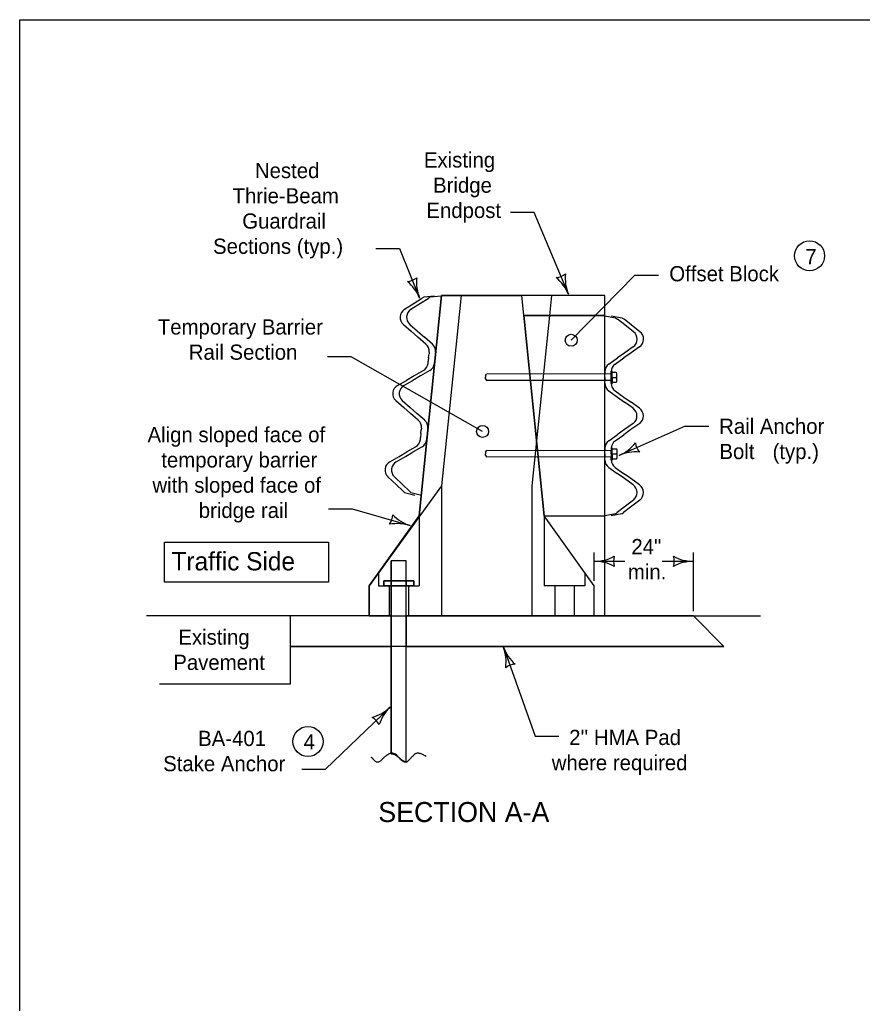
# Model space of a CAD drawing. Extents: x 10028 to 81668, y 3581 to 11018.
# Drawn here: x 17333 to 18174, y 8962 to 9944 of the extents above; entities that cross this region are included whole.
import ezdxf

# ---------------------------------------------------------------- set-up
doc = ezdxf.new("R2010")
doc.units = 0
for name, color, linetype in [('conPaving', 7, 'Continuous'), ('dsnCellsNorthArrow', 7, 'Continuous'), ('dsnTextTabulation', 7, 'Continuous'), ('Level 41', 7, 'Continuous'), ('Level 9', 7, 'Continuous'), ('SheetBorder', 7, 'Continuous')]:
    doc.layers.add(name, color=color, linetype=linetype)

msp = doc.modelspace()

# ---------------------------------------------------------------- linework, layer by layer
at = {"layer": 'conPaving'}
for p, q in [((17753.7, 9478.52), (17753.7, 9348.52)), ((17844.13, 9478.52), (17844.13, 9348.52))]:
    msp.add_line(p, q, dxfattribs=at)
at = {"layer": 'dsnCellsNorthArrow'}
for p, q in [((17773.43, 9668.41), (17753.7, 9478.52)), ((17916.97, 9668.41), (17773.43, 9668.41)), ((17863.86, 9668.41), (17861.79, 9648.52)), ((17916.97, 9348.63), (17916.97, 9668.41)), ((17861.79, 9648.52), (17844.13, 9478.52)), ((17753.7, 9478.52), (17681.45, 9378.52)), ((17681.45, 9348.52), (17681.45, 9378.52))]:
    msp.add_line(p, q, dxfattribs=at)
at = {"layer": 'dsnTextTabulation'}
for p, q in [((17846.24, 9751.44), (17822.63, 9751.44)), ((17880.56, 9669.84), (17846.24, 9751.44)), ((17688.2, 9715.55), (17711.8, 9715.55)), ((17711.8, 9715.55), (17732.03, 9665.97)), ((17883.39, 9623.84), (17946.85, 9688.92)), ((17946.85, 9688.92), (17970.49, 9688.92)), ((17731.45, 9448.52), (17753.95, 9668.52)), ((17736.25, 9666.95), (17734.02, 9665.54)), ((17746.96, 9667.77), (17736.25, 9666.95)), ((17742.65, 9666.95), (17740.42, 9665.54)), ((17753.36, 9667.77), (17742.65, 9666.95)), ((17753.95, 9668.52), (17833.95, 9668.52)), ((17856.45, 9448.52), (17833.95, 9668.52)), ((17716.98, 9654.79), (17726.48, 9660.78)), ((17723.38, 9654.79), (17732.88, 9660.78)), ((17726.48, 9660.78), (17734.02, 9665.54)), ((17732.88, 9660.78), (17740.42, 9665.54)), ((17917.13, 9648.3), (17927.71, 9646.42)), ((17923.53, 9648.3), (17934.1, 9646.42)), ((17927.71, 9646.42), (17929.79, 9644.8)), ((17934.1, 9646.42), (17936.18, 9644.8)), ((17715.82, 9639.74), (17723.62, 9632.93)), ((17722.22, 9639.74), (17730.02, 9632.93)), ((17936.82, 9639.31), (17929.79, 9644.8)), ((17943.21, 9639.31), (17936.18, 9644.8)), ((17945.67, 9632.4), (17936.82, 9639.31)), ((17952.07, 9632.4), (17943.21, 9639.31)), ((17723.62, 9632.93), (17730.33, 9627.08)), ((17730.02, 9632.93), (17736.73, 9627.08)), ((17738.34, 9620.09), (17730.33, 9627.08)), ((17744.74, 9620.09), (17736.73, 9627.08)), ((17945.33, 9617.31), (17936.89, 9611.32)), ((17951.72, 9617.31), (17943.29, 9611.32)), ((17663.62, 9607.48), (17640.02, 9607.48)), ((17794.92, 9532.77), (17663.62, 9607.48)), ((17740.98, 9606.45), (17741.36, 9610.33)), ((17741.53, 9612.08), (17741.36, 9610.33)), ((17747.38, 9606.45), (17747.76, 9610.33)), ((17747.93, 9612.08), (17747.76, 9610.33)), ((17936.89, 9611.32), (17929.62, 9606.16)), ((17943.29, 9611.32), (17936.02, 9606.16)), ((17740.44, 9600.82), (17740.63, 9602.86)), ((17741, 9606.59), (17740.63, 9602.86)), ((17746.83, 9600.82), (17747.03, 9602.86)), ((17747.39, 9606.59), (17747.03, 9602.86)), ((17920.96, 9600), (17929.62, 9606.16)), ((17927.36, 9600), (17936.02, 9606.16)), ((17726.57, 9588.28), (17718.85, 9583.83)), ((17732.97, 9588.28), (17725.25, 9583.83)), ((17735.76, 9593.58), (17726.57, 9588.28)), ((17742.16, 9593.58), (17732.97, 9588.28)), ((17916.97, 9586.69), (17916.98, 9590.59)), ((17916.99, 9592.35), (17916.98, 9590.59)), ((17923.37, 9586.69), (17923.38, 9590.59)), ((17923.39, 9592.35), (17923.38, 9590.59)), ((17709.87, 9578.65), (17718.85, 9583.83)), ((17716.26, 9578.65), (17725.25, 9583.83)), ((17916.96, 9581.03), (17916.97, 9583.08)), ((17916.97, 9586.83), (17916.97, 9583.08)), ((17923.37, 9586.83), (17923.36, 9583.08)), ((17923.36, 9581.03), (17923.36, 9583.08)), ((17920.89, 9573.36), (17929.51, 9567.18)), ((17927.29, 9573.36), (17935.9, 9567.18)), ((17708.12, 9563.63), (17716.2, 9556.59)), ((17714.52, 9563.63), (17722.6, 9556.59)), ((17929.51, 9567.18), (17936.74, 9561.98)), ((17935.9, 9567.18), (17943.14, 9561.98)), ((17945.17, 9555.93), (17936.74, 9561.98)), ((17951.57, 9555.93), (17943.14, 9561.98)), ((17716.2, 9556.59), (17722.91, 9550.73)), ((17722.6, 9556.59), (17729.31, 9550.73)), ((17730.65, 9543.98), (17722.91, 9550.73)), ((17737.04, 9543.98), (17729.31, 9550.73)), ((17945.41, 9540.82), (17936.67, 9534.61)), ((17951.81, 9540.82), (17943.07, 9534.61)), ((17733.32, 9530.66), (17732.96, 9526.93)), ((17733.32, 9530.66), (17733.68, 9534.4)), ((17733.84, 9535.98), (17733.68, 9534.4)), ((17739.72, 9530.66), (17739.35, 9526.93)), ((17739.72, 9530.66), (17740.08, 9534.4)), ((17740.23, 9535.98), (17740.08, 9534.4)), ((17921.04, 9523.51), (17929.41, 9529.45)), ((17927.44, 9523.51), (17935.8, 9529.45)), ((17936.67, 9534.61), (17929.41, 9529.45)), ((17997.16, 9537.94), (17931.26, 9508.86)), ((17943.07, 9534.61), (17935.8, 9529.45)), ((17997.16, 9537.94), (18020.77, 9537.94)), ((17732.74, 9524.71), (17732.96, 9526.93)), ((17739.14, 9524.71), (17739.35, 9526.93)), ((17711.45, 9507.9), (17719.17, 9512.35)), ((17717.85, 9507.9), (17725.57, 9512.35)), ((17728.06, 9517.47), (17719.17, 9512.35)), ((17734.46, 9517.47), (17725.57, 9512.35)), ((17917.05, 9510.52), (17917.06, 9514.27)), ((17917.05, 9510.52), (17917.05, 9506.76)), ((17917.07, 9515.86), (17917.06, 9514.27)), ((17923.45, 9510.52), (17923.44, 9506.76)), ((17923.45, 9510.52), (17923.46, 9514.27)), ((17923.47, 9515.86), (17923.46, 9514.27)), ((17702.17, 9502.55), (17711.45, 9507.9)), ((17708.57, 9502.55), (17717.85, 9507.9)), ((17917.04, 9504.54), (17917.05, 9506.76)), ((17923.44, 9504.54), (17923.44, 9506.76)), ((17920.97, 9496.87), (17929.31, 9490.88)), ((17927.37, 9496.87), (17935.71, 9490.88)), ((17936.55, 9485.69), (17929.31, 9490.88)), ((17942.95, 9485.69), (17935.71, 9490.88)), ((17700.4, 9487.55), (17708.81, 9479.61)), ((17706.8, 9487.55), (17715.2, 9479.61)), ((17708.81, 9479.61), (17715.29, 9473.48)), ((17715.2, 9479.61), (17721.69, 9473.48)), ((17945.25, 9479.44), (17936.55, 9485.69)), ((17951.65, 9479.44), (17942.95, 9485.69)), ((17716.96, 9471.9), (17715.29, 9473.48)), ((17716.96, 9471.9), (17727.31, 9469.03)), ((17723.36, 9471.9), (17721.69, 9473.48)), ((17723.36, 9471.9), (17733.71, 9469.03)), ((17945.52, 9464.34), (17936.36, 9457.28)), ((17951.91, 9464.34), (17942.76, 9457.28)), ((17640.93, 9455.58), (17664.54, 9455.58)), ((17664.54, 9455.58), (17722.64, 9438.73)), ((17927.48, 9450.42), (17916.9, 9448.59)), ((17933.88, 9450.42), (17923.29, 9448.59)), ((17927.48, 9450.42), (17929.3, 9451.82)), ((17936.36, 9457.28), (17929.3, 9451.83)), ((17933.88, 9450.42), (17935.7, 9451.82)), ((17942.76, 9457.28), (17935.7, 9451.83)), ((17681.45, 9378.52), (17731.45, 9448.52)), ((17906.45, 9378.52), (17856.45, 9448.52)), ((17906.45, 9383.51), (17906.45, 9411.87)), ((18005.49, 9353.28), (18005.49, 9411.87)), ((17906.45, 9403.11), (17936.86, 9403.11)), ((17974.18, 9403.11), (18005.49, 9403.11)), ((17681.45, 9348.52), (17681.45, 9378.52)), ((17906.45, 9348.52), (17906.45, 9378.52)), ((17681.45, 9348.52), (17906.45, 9348.52)), ((17815.75, 9317.4), (17847.38, 9228.36)), ((17638.11, 9195.72), (17702.53, 9257.52)), ((17847.38, 9228.36), (17870.98, 9228.36)), ((17614.5, 9195.72), (17638.11, 9195.72))]:
    msp.add_line(p, q, dxfattribs=at)
for centre in [(18121.45, 9708.22), (17620.5, 9223.19)]:
    msp.add_circle(centre, 15, dxfattribs=at)
for centre, radius, start, end in [((17718.57, 9698.97), 16.42, 274.46679, 309.93349), ((17771.38, 9682.03), 42.5, 174.12765, 202.20014), ((17867.11, 9702.84), 16.42, 274.42912, 309.89582), ((17841.2, 9653.8), 42.5, 22.16247, 50.23496), ((17919.92, 9685.87), 42.5, 174.08998, 202.16247), ((17692.68, 9649.92), 42.5, 22.20014, 50.27263), ((17914.25, 9547.8), 42.5, 293.59825, 321.67074), ((17963.92, 9523.12), 16.42, 185.8649, 221.3316), ((17948.28, 9469.91), 42.5, 85.52576, 113.59825), ((17688.71, 9449.63), 16.42, 324.45544, 359.92214), ((17709.64, 9398.27), 42.5, 72.18879, 100.26128), ((17735.64, 9479.19), 42.5, 224.1163, 252.18879), ((17906.45, 9445.61), 42.5, 270, 298.07249), ((17906.45, 9360.61), 42.5, 61.92751, 90), ((17942.09, 9403.11), 16.42, 162.26665, 197.73335), ((17969.85, 9403.11), 16.42, 342.26665, 17.73335), ((18005.49, 9445.61), 42.5, 241.92751, 270), ((18005.49, 9360.61), 42.5, 90, 118.07249), ((17855.63, 9332.08), 42.5, 200.20763, 228.28012), ((17775.86, 9302.72), 42.5, 352.13514, 20.20763), ((17828.05, 9283.96), 16.42, 92.47427, 127.94098), ((17673.1, 9288.19), 42.5, 285.73709, 313.80957), ((17731.95, 9226.85), 42.5, 133.80957, 161.88206), ((17676.81, 9232.85), 16.42, 26.07622, 61.54292)]:
    msp.add_arc(centre, radius, start, end, dxfattribs=at)
for centre, major_axis, start_param, end_param in [((17722.06, 9646.83), (9.43, -0.92), 2.229659, 4.096128), ((17728.46, 9646.83), (9.43, -0.92), 2.229659, 4.096128), ((17939.82, 9624.98), (-9.48, 0.02), 2.187057, 4.053527), ((17946.22, 9624.98), (-9.48, 0.02), 2.187057, 4.053527), ((17732.1, 9613), (9.43, -0.92), 0, 0.954538), ((17738.5, 9613), (9.43, -0.92), 0, 0.954538), ((17731, 9601.74), (-9.43, 0.92), 2.187055, 3.141593), ((17737.4, 9601.74), (-9.43, 0.92), 2.187055, 3.141593), ((17926.47, 9592.33), (-9.48, 0.02), 5.328647, 6.283185), ((17932.86, 9592.33), (-9.48, 0.02), 5.328647, 6.283185), ((17714.62, 9570.49), (-9.43, 0.92), 5.32865, 7.195119), ((17721.02, 9570.49), (-9.43, 0.92), 5.32865, 7.195119), ((17926.44, 9581.01), (9.48, -0.02), 3.141593, 4.096131), ((17932.83, 9581.01), (9.48, -0.02), 3.141593, 4.096131), ((17939.62, 9548.29), (9.48, -0.02), 5.371251, 7.237721), ((17946.02, 9548.29), (9.48, -0.02), 5.371251, 7.237721), ((17724.4, 9536.9), (9.43, -0.92), 0, 0.954538), ((17730.8, 9536.9), (9.43, -0.92), 0, 0.954538), ((17723.31, 9525.63), (-9.43, 0.92), 2.187055, 3.141593), ((17729.7, 9525.63), (-9.43, 0.92), 2.187055, 3.141593), ((17926.55, 9515.83), (-9.48, 0.02), 5.328647, 6.283185), ((17932.94, 9515.83), (-9.48, 0.02), 5.328647, 6.283185), ((17706.93, 9494.38), (-9.43, 0.92), 5.32865, 7.195119), ((17713.32, 9494.38), (-9.43, 0.92), 5.32865, 7.195119), ((17926.52, 9504.52), (9.48, -0.02), 3.141593, 4.096131), ((17932.92, 9504.52), (9.48, -0.02), 3.141593, 4.096131), ((17939.7, 9471.79), (9.48, -0.02), 5.371251, 7.237721), ((17946.1, 9471.79), (9.48, -0.02), 5.371251, 7.237721)]:
    msp.add_ellipse(centre, major_axis=major_axis, ratio=0.994906, start_param=start_param, end_param=end_param, dxfattribs=at)
at = {"layer": 'Level 41'}
for p, q in [((17731.45, 9448.52), (17731.45, 9378.52)), ((17856.45, 9448.52), (17856.45, 9378.52)), ((17690.98, 9391.86), (17690.98, 9378.52)), ((17896.92, 9391.86), (17896.92, 9378.52)), ((17690.98, 9378.52), (17731.45, 9378.52)), ((17701.62, 9378.52), (17701.62, 9348.52)), ((17720.82, 9378.52), (17720.82, 9348.52)), ((17896.92, 9378.52), (17856.45, 9378.52)), ((17867.09, 9378.52), (17867.09, 9348.52)), ((17886.29, 9378.52), (17886.29, 9348.52))]:
    msp.add_line(p, q, dxfattribs=at)
at = {"layer": 'Level 9'}
for p, q in [((17753.95, 9668.52), (17731.45, 9448.52)), ((17833.95, 9668.52), (17753.95, 9668.52)), ((17856.45, 9448.52), (17833.95, 9668.52)), ((17836, 9648.52), (17916.97, 9648.52)), ((17916.97, 9648.52), (17836, 9648.52)), ((17836, 9648.52), (17856.45, 9448.52)), ((17916.97, 9448.52), (17916.97, 9648.52)), ((17797.76, 9588.48), (17798.94, 9590.1)), ((17797.76, 9588.48), (17797.76, 9586.86)), ((17923.38, 9590.07), (17799.08, 9590.28)), ((17923.36, 9580.76), (17923.38, 9592.91)), ((17923.37, 9586.83), (17923.38, 9590.07)), ((17923.38, 9592.91), (17924.28, 9592.91)), ((17924.26, 9581.97), (17924.28, 9591.69)), ((17924.27, 9586.83), (17924.28, 9592.91)), ((17928.12, 9591.69), (17924.28, 9591.69)), ((17929.07, 9585.96), (17929.08, 9590.82)), ((17797.76, 9585.24), (17797.76, 9586.86)), ((17797.76, 9585.24), (17798.93, 9583.62)), ((17923.37, 9583.59), (17798.8, 9583.8)), ((17924.26, 9580.76), (17923.36, 9580.76)), ((17924.27, 9586.83), (17924.26, 9580.76)), ((17924.26, 9581.97), (17928.1, 9581.97)), ((17924.27, 9586.83), (17928.11, 9586.83)), ((17929.06, 9582.83), (17929.07, 9585.96)), ((17797.89, 9512.02), (17799.07, 9513.64)), ((17797.89, 9512.02), (17797.89, 9510.4)), ((17797.89, 9508.78), (17797.89, 9510.4)), ((17797.89, 9508.78), (17799.06, 9507.16)), ((17923.51, 9513.62), (17799.21, 9513.82)), ((17923.49, 9504.3), (17923.51, 9516.45)), ((17923.5, 9510.38), (17923.51, 9513.62)), ((17923.51, 9516.45), (17924.41, 9516.45)), ((17924.39, 9505.51), (17924.41, 9515.23)), ((17924.4, 9510.37), (17924.39, 9504.3)), ((17924.4, 9510.37), (17924.41, 9516.45)), ((17924.4, 9510.37), (17928.24, 9510.37)), ((17928.25, 9515.23), (17924.41, 9515.23)), ((17929.19, 9506.37), (17929.2, 9509.5)), ((17929.2, 9509.5), (17929.21, 9514.36)), ((17923.5, 9507.14), (17798.93, 9507.34)), ((17924.39, 9504.3), (17923.49, 9504.3)), ((17924.39, 9505.51), (17928.23, 9505.51)), ((17731.45, 9448.52), (17681.45, 9378.52)), ((17906.45, 9378.52), (17856.45, 9448.52)), ((17856.45, 9448.52), (17916.97, 9448.52)), ((17856.45, 9448.52), (17916.97, 9448.52)), ((17718.72, 9403.52), (17703.72, 9403.52)), ((17703.72, 9403.52), (17703.72, 9383.52)), ((17718.72, 9403.52), (17703.72, 9403.52)), ((17703.72, 9210.9), (17703.72, 9403.52)), ((17718.72, 9383.52), (17718.72, 9403.52)), ((17718.72, 9203.34), (17718.72, 9403.52)), ((17696.22, 9383.52), (17696.22, 9378.52)), ((17703.72, 9383.52), (17696.22, 9383.52)), ((17696.22, 9378.52), (17696.22, 9383.52)), ((17703.72, 9383.52), (17718.72, 9383.52)), ((17718.72, 9383.52), (17703.72, 9383.52)), ((17703.72, 9383.52), (17703.72, 9378.52)), ((17703.72, 9378.52), (17703.72, 9383.52)), ((17718.72, 9383.52), (17718.72, 9378.52)), ((17718.72, 9378.52), (17718.72, 9383.52)), ((17681.45, 9378.52), (17681.45, 9348.52)), ((17696.22, 9378.52), (17703.72, 9378.52)), ((17718.72, 9378.52), (17703.72, 9378.52)), ((17703.72, 9378.52), (17703.72, 9210.9)), ((17703.72, 9378.52), (17718.72, 9378.52)), ((17718.72, 9203.34), (17718.72, 9378.52)), ((17718.72, 9378.52), (17726.22, 9378.52)), ((17906.45, 9348.52), (17906.45, 9378.52)), ((17602.74, 9348.52), (17459.32, 9348.52)), ((17602.74, 9348.52), (17602.74, 9318.08)), ((17681.45, 9348.52), (17602.74, 9348.52)), ((17681.45, 9348.52), (17602.74, 9348.52)), ((17602.74, 9348.52), (17602.74, 9280.52)), ((17701.62, 9348.52), (17681.45, 9348.52)), ((17681.45, 9348.52), (17906.45, 9348.52)), ((17703.72, 9348.52), (17701.62, 9348.52)), ((17703.72, 9318.08), (17703.72, 9348.52)), ((17720.82, 9348.52), (17718.72, 9348.52)), ((17718.72, 9348.52), (17718.72, 9318.08)), ((17867.09, 9348.52), (17720.82, 9348.52)), ((17886.29, 9348.52), (17867.09, 9348.52)), ((17906.45, 9348.52), (17886.29, 9348.52)), ((18005.49, 9348.52), (17906.45, 9348.52)), ((17906.45, 9348.52), (18072.54, 9348.52)), ((18035.93, 9318.08), (18005.49, 9348.52)), ((18005.49, 9348.52), (18035.93, 9318.08)), ((17602.74, 9318.08), (17703.72, 9318.08)), ((18035.93, 9318.08), (17602.74, 9318.08)), ((17718.72, 9318.08), (18035.93, 9318.08)), ((17602.74, 9280.52), (17472.29, 9280.52))]:
    msp.add_line(p, q, dxfattribs=at)
msp.add_lwpolyline([(17477.34, 9422.22), (17641, 9422.22), (17641, 9382.22), (17477.34, 9382.22)], close=True, dxfattribs=at)
for points in [[(17696.22, 9383.52), (17726.22, 9383.52), (17726.22, 9378.52), (17696.22, 9378.52)], [(17726.22, 9378.52), (17726.22, 9383.52), (17718.72, 9383.52)]]:
    msp.add_lwpolyline(points, dxfattribs=at)
for centre in [(17883.39, 9623.84), (17794.92, 9532.77)]:
    msp.add_circle(centre, 5.96, dxfattribs=at)
for centre, start_param, end_param in [((17928.11, 9587.69), 1.570796, 3.141593), ((17928.12, 9590.82), 3.141593, 4.712389), ((17928.1, 9582.83), 1.570796, 3.141593), ((17928.11, 9585.96), 3.141593, 4.712389), ((17928.24, 9511.23), 1.570796, 3.141593), ((17928.24, 9509.5), 3.141593, 4.712389), ((17928.25, 9514.36), 3.141593, 4.712389), ((17928.23, 9506.37), 1.570796, 3.141593)]:
    msp.add_ellipse(centre, major_axis=(-0.96, 0.002), ratio=0.899999, start_param=start_param, end_param=end_param, dxfattribs=at)
for points, degree in [([(17738.45, 9208.16), (17730.24, 9213.53), (17723.29, 9206.9), (17717.3, 9200.27), (17706.56, 9212.9), (17698.35, 9209.42), (17690.15, 9200.59), (17683.83, 9207.53), (17683.89, 9207.51)], 2), ([(17703.72, 9210.9), (17704.76, 9210.96), (17708.85, 9210.2), (17714.73, 9203.29), (17718.02, 9203.17), (17718.72, 9203.34)], 3)]:
    msp.add_open_spline(points, degree=degree, dxfattribs=at)
at = {"layer": 'SheetBorder'}
msp.add_lwpolyline([(17332.52, 9944.02), (20467.53, 9944.02), (20467.53, 7924.02), (17332.52, 7924.02)], close=True, dxfattribs=at)

# ---------------------------------------------------------------- texts
at = {"layer": 'dsnCellsNorthArrow'}
for s, height, p in [('Existing', 15.2, (17736.26, 9796.37)), ('Nested ', 15.2, (17567.5, 9785.75)), ('Bridge', 15.2, (17745.43, 9771.17)), ('Thrie-Beam', 15.2, (17545.16, 9760.55)), ('Endpost', 15.2, (17738.77, 9745.97)), ('Guardrail ', 15.2, (17554.84, 9735.35)), ('Sections (typ.)', 15.2, (17525.69, 9710.15)), ('Offset Block', 15.2, (17981.39, 9682.75)), ('Temporary Barrier', 15.2, (17470.51, 9629.6)), ('Rail Section', 15.2, (17501.46, 9604.4)), ('Rail Anchor', 15.2, (18031.15, 9530.43)), ('Align sloped face of', 15.2, (17460.22, 9522.02)), ('Bolt ', 15.2, (18031.43, 9505.23)), ('(typ.)', 15.2, (18084.53, 9505.23)), ('temporary barrier', 15.2, (17473.97, 9496.82)), ('with sloped face of ', 15.2, (17465.13, 9471.62)), ('bridge rail', 15.2, (17511.39, 9446.42)), ('24"', 15.2, (17943.51, 9410.21)), ('Traffic Side', 18.24, (17484.19, 9394.07)), ('min.', 15.2, (17940.01, 9385.01)), ('Existing', 15.2, (17491.02, 9319.82)), ('Pavement', 15.2, (17485.96, 9294.62)), ('BA-401', 15.2, (17510.76, 9218.68)), ("2'' HMA Pad", 15.2, (17881.35, 9219.66)), ('Stake Anchor', 15.2, (17475.85, 9193.48)), ('where required', 15.2, (17863.97, 9194.46)), ('SECTION A-A', 20, (17690.71, 9142.74))]:
    msp.add_text(s, height=height, dxfattribs=at).set_placement(p)
at = {"layer": 'dsnTextTabulation'}
for s, p in [('7', (18117.24, 9699.86)), ('4', (17616.13, 9215.29))]:
    msp.add_text(s, height=15.2, dxfattribs=at).set_placement(p)

doc.saveas('drawing.dxf')
